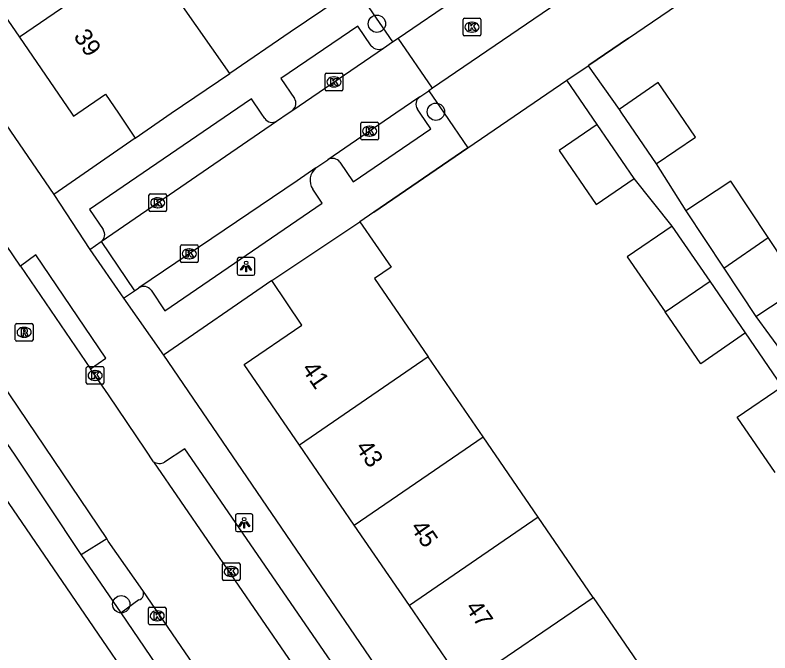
# Model space of a CAD drawing. Extents: x 157466 to 158888, y 383063 to 384677.
# Drawn here: x 158131.78 to 158174.52, y 383719.45 to 383755.56 of the extents above; entities that cross this region are included whole.
import ezdxf

# ---------------------------------------------------------------- set-up
doc = ezdxf.new("R2010")
doc.units = 0
for name, color, linetype in [('IMGEO_Boom', 7, 'Continuous'), ('IMGEO_Kolk', 7, 'Continuous'), ('IMGEO_Lichtpunt', 7, 'Continuous'), ('IMGEO_Muur', 7, 'Continuous'), ('IMGEO_Pand', 7, 'Continuous'), ('IMGEO_Pand_nummerreeks', 7, 'Continuous'), ('IMGEO_Parkeervlak_open', 7, 'Continuous'), ('IMGEO_Rijbaan_lokaal_open', 7, 'Continuous'), ('IMGEO_Rioolput', 7, 'Continuous'), ('IMGEO_Voetpad_open', 7, 'Continuous')]:
    doc.layers.add(name, color=color, linetype=linetype)

msp = doc.modelspace()

# ---------------------------------------------------------------- linework, layer by layer
at = {"layer": 'IMGEO_Boom'}
for centre in [(158152.265, 383755.066), (158155.606, 383750.086), (158137.79, 383722.2)]:
    msp.add_circle(centre, 0.489, dxfattribs=at)
at = {"layer": 'IMGEO_Kolk'}
for p, q in [((158157.15, 383754.45), (158157.15, 383755.302)), ((158157.225, 383755.376), (158158.077, 383755.376)), ((158158.151, 383755.302), (158158.151, 383754.45)), ((158157.638, 383755.156), (158157.663, 383755.156)), ((158158.077, 383754.376), (158157.225, 383754.376)), ((158157.661, 383754.596), (158157.636, 383754.596)), ((158149.41, 383752.274), (158150.262, 383752.274)), ((158149.335, 383751.348), (158149.335, 383752.2)), ((158149.823, 383752.054), (158149.848, 383752.054)), ((158150.336, 383752.2), (158150.336, 383751.348)), ((158149.846, 383751.494), (158149.821, 383751.494)), ((158150.262, 383751.274), (158149.41, 383751.274)), ((158151.355, 383748.56), (158151.355, 383749.412)), ((158151.43, 383749.486), (158152.282, 383749.486)), ((158151.843, 383749.266), (158151.868, 383749.266)), ((158152.356, 383749.412), (158152.356, 383748.56)), ((158152.282, 383748.486), (158151.43, 383748.486)), ((158151.866, 383748.706), (158151.841, 383748.706)), ((158139.435, 383745.431), (158140.287, 383745.431)), ((158139.36, 383744.505), (158139.36, 383745.357)), ((158139.848, 383745.211), (158139.873, 383745.211)), ((158140.361, 383745.357), (158140.361, 383744.505)), ((158139.871, 383744.651), (158139.846, 383744.651)), ((158140.287, 383744.431), (158139.435, 383744.431)), ((158141.143, 383741.617), (158141.143, 383742.469)), ((158141.218, 383742.543), (158142.07, 383742.543)), ((158142.144, 383742.469), (158142.144, 383741.617)), ((158141.631, 383742.323), (158141.656, 383742.323)), ((158141.654, 383741.763), (158141.629, 383741.763)), ((158142.07, 383741.543), (158141.218, 383741.543)), ((158135.813, 383734.728), (158135.813, 383735.58)), ((158135.888, 383735.654), (158136.74, 383735.654)), ((158136.814, 383735.58), (158136.814, 383734.728)), ((158136.301, 383735.434), (158136.326, 383735.434)), ((158136.324, 383734.874), (158136.299, 383734.874)), ((158136.74, 383734.654), (158135.888, 383734.654)), ((158143.515, 383723.625), (158143.515, 383724.477)), ((158143.59, 383724.551), (158144.442, 383724.551)), ((158144.516, 383724.477), (158144.516, 383723.625)), ((158144.003, 383724.331), (158144.028, 383724.331)), ((158144.026, 383723.771), (158144.001, 383723.771)), ((158144.442, 383723.551), (158143.59, 383723.551)), ((158139.325, 383721.116), (158139.325, 383721.968)), ((158139.4, 383722.042), (158140.252, 383722.042)), ((158140.326, 383721.968), (158140.326, 383721.116)), ((158139.813, 383721.822), (158139.838, 383721.822)), ((158140.252, 383721.042), (158139.4, 383721.042)), ((158139.836, 383721.262), (158139.811, 383721.262))]:
    msp.add_line(p, q, dxfattribs=at)
for points in [[(158157.15, 383754.45), (158157.15, 383755.302)], [(158157.225, 383755.376), (158158.077, 383755.376)], [(158158.151, 383755.302), (158158.151, 383754.45)], [(158157.471, 383755.076), (158157.594, 383755.076), (158157.594, 383754.925), (158157.724, 383755.076), (158157.888, 383755.076), (158157.742, 383754.925), (158157.895, 383754.676), (158157.743, 383754.676), (158157.658, 383754.84), (158157.594, 383754.773), (158157.594, 383754.676), (158157.471, 383754.676), (158157.471, 383755.076)], [(158158.077, 383754.376), (158157.225, 383754.376)], [(158149.41, 383752.274), (158150.262, 383752.274)], [(158149.335, 383751.348), (158149.335, 383752.2)], [(158149.656, 383751.974), (158149.779, 383751.974), (158149.779, 383751.823), (158149.909, 383751.974), (158150.073, 383751.974), (158149.927, 383751.823), (158150.08, 383751.574), (158149.928, 383751.574), (158149.843, 383751.738), (158149.779, 383751.671), (158149.779, 383751.574), (158149.656, 383751.574), (158149.656, 383751.974)], [(158150.336, 383752.2), (158150.336, 383751.348)], [(158150.262, 383751.274), (158149.41, 383751.274)], [(158151.355, 383748.56), (158151.355, 383749.412)], [(158151.43, 383749.486), (158152.282, 383749.486)], [(158152.356, 383749.412), (158152.356, 383748.56)], [(158151.676, 383749.186), (158151.799, 383749.186), (158151.799, 383749.035), (158151.929, 383749.186), (158152.093, 383749.186), (158151.947, 383749.035), (158152.1, 383748.786), (158151.948, 383748.786), (158151.863, 383748.95), (158151.799, 383748.883), (158151.799, 383748.786), (158151.676, 383748.786), (158151.676, 383749.186)], [(158152.282, 383748.486), (158151.43, 383748.486)], [(158139.435, 383745.431), (158140.287, 383745.431)], [(158139.36, 383744.505), (158139.36, 383745.357)], [(158139.681, 383745.131), (158139.804, 383745.131), (158139.804, 383744.98), (158139.934, 383745.131), (158140.098, 383745.131), (158139.952, 383744.98), (158140.105, 383744.731), (158139.953, 383744.731), (158139.868, 383744.895), (158139.804, 383744.828), (158139.804, 383744.731), (158139.681, 383744.731), (158139.681, 383745.131)], [(158140.361, 383745.357), (158140.361, 383744.505)], [(158140.287, 383744.431), (158139.435, 383744.431)], [(158141.143, 383741.617), (158141.143, 383742.469)], [(158141.218, 383742.543), (158142.07, 383742.543)], [(158142.144, 383742.469), (158142.144, 383741.617)], [(158141.464, 383742.243), (158141.587, 383742.243), (158141.587, 383742.092), (158141.717, 383742.243), (158141.881, 383742.243), (158141.735, 383742.092), (158141.888, 383741.843), (158141.736, 383741.843), (158141.651, 383742.007), (158141.587, 383741.94), (158141.587, 383741.843), (158141.464, 383741.843), (158141.464, 383742.243)], [(158142.07, 383741.543), (158141.218, 383741.543)], [(158135.813, 383734.728), (158135.813, 383735.58)], [(158135.888, 383735.654), (158136.74, 383735.654)], [(158136.814, 383735.58), (158136.814, 383734.728)], [(158136.134, 383735.354), (158136.257, 383735.354), (158136.257, 383735.203), (158136.387, 383735.354), (158136.551, 383735.354), (158136.405, 383735.203), (158136.558, 383734.954), (158136.406, 383734.954), (158136.321, 383735.118), (158136.257, 383735.051), (158136.257, 383734.954), (158136.134, 383734.954), (158136.134, 383735.354)], [(158136.74, 383734.654), (158135.888, 383734.654)], [(158143.515, 383723.625), (158143.515, 383724.477)], [(158143.59, 383724.551), (158144.442, 383724.551)], [(158144.516, 383724.477), (158144.516, 383723.625)], [(158143.836, 383724.251), (158143.959, 383724.251), (158143.959, 383724.1), (158144.089, 383724.251), (158144.253, 383724.251), (158144.107, 383724.1), (158144.26, 383723.851), (158144.108, 383723.851), (158144.023, 383724.015), (158143.959, 383723.948), (158143.959, 383723.851), (158143.836, 383723.851), (158143.836, 383724.251)], [(158144.442, 383723.551), (158143.59, 383723.551)], [(158139.325, 383721.116), (158139.325, 383721.968)], [(158139.4, 383722.042), (158140.252, 383722.042)], [(158140.326, 383721.968), (158140.326, 383721.116)], [(158139.646, 383721.742), (158139.769, 383721.742), (158139.769, 383721.591), (158139.899, 383721.742), (158140.063, 383721.742), (158139.917, 383721.591), (158140.07, 383721.342), (158139.918, 383721.342), (158139.833, 383721.506), (158139.769, 383721.439), (158139.769, 383721.342), (158139.646, 383721.342), (158139.646, 383721.742)], [(158140.252, 383721.042), (158139.4, 383721.042)]]:
    msp.add_lwpolyline(points, dxfattribs=at)
for centre, start, end in [((158157.227, 383755.3), 91.552, 178.448), ((158157.227, 383755.3), 91.552, 178.448), ((158158.075, 383755.3), 1.552, 88.448), ((158158.075, 383755.3), 1.552, 88.448), ((158157.227, 383754.452), 181.552, 268.448), ((158157.227, 383754.452), 181.552, 268.448), ((158158.075, 383754.452), 271.552, 358.448), ((158158.075, 383754.452), 271.552, 358.448), ((158149.412, 383752.198), 91.552, 178.448), ((158149.412, 383752.198), 91.552, 178.448), ((158150.26, 383752.198), 1.552, 88.448), ((158150.26, 383752.198), 1.552, 88.448), ((158149.412, 383751.35), 181.552, 268.448), ((158149.412, 383751.35), 181.552, 268.448), ((158150.26, 383751.35), 271.552, 358.448), ((158150.26, 383751.35), 271.552, 358.448), ((158151.432, 383749.41), 91.552, 178.448), ((158151.432, 383749.41), 91.552, 178.448), ((158152.28, 383749.41), 1.552, 88.448), ((158152.28, 383749.41), 1.552, 88.448), ((158151.432, 383748.562), 181.552, 268.448), ((158151.432, 383748.562), 181.552, 268.448), ((158152.28, 383748.562), 271.552, 358.448), ((158152.28, 383748.562), 271.552, 358.448), ((158139.437, 383745.355), 91.552, 178.448), ((158139.437, 383745.355), 91.552, 178.448), ((158140.285, 383745.355), 1.552, 88.448), ((158140.285, 383745.355), 1.552, 88.448), ((158139.437, 383744.507), 181.552, 268.448), ((158139.437, 383744.507), 181.552, 268.448), ((158140.285, 383744.507), 271.552, 358.448), ((158140.285, 383744.507), 271.552, 358.448), ((158141.22, 383742.467), 91.552, 178.448), ((158141.22, 383742.467), 91.552, 178.448), ((158142.068, 383742.467), 1.552, 88.448), ((158142.068, 383742.467), 1.552, 88.448), ((158141.22, 383741.619), 181.552, 268.448), ((158141.22, 383741.619), 181.552, 268.448), ((158142.068, 383741.619), 271.552, 358.448), ((158142.068, 383741.619), 271.552, 358.448), ((158135.89, 383735.578), 91.552, 178.448), ((158135.89, 383735.578), 91.552, 178.448), ((158136.738, 383735.578), 1.552, 88.448), ((158136.738, 383735.578), 1.552, 88.448), ((158135.89, 383734.73), 181.552, 268.448), ((158135.89, 383734.73), 181.552, 268.448), ((158136.738, 383734.73), 271.552, 358.448), ((158136.738, 383734.73), 271.552, 358.448), ((158143.592, 383724.475), 91.552, 178.448), ((158143.592, 383724.475), 91.552, 178.448), ((158144.44, 383724.475), 1.552, 88.448), ((158144.44, 383724.475), 1.552, 88.448), ((158143.592, 383723.627), 181.552, 268.448), ((158143.592, 383723.627), 181.552, 268.448), ((158144.44, 383723.627), 271.552, 358.448), ((158144.44, 383723.627), 271.552, 358.448), ((158139.402, 383721.966), 91.552, 178.448), ((158139.402, 383721.966), 91.552, 178.448), ((158140.25, 383721.966), 1.552, 88.448), ((158140.25, 383721.966), 1.552, 88.448), ((158139.402, 383721.118), 181.552, 268.448), ((158139.402, 383721.118), 181.552, 268.448), ((158140.25, 383721.118), 271.552, 358.448), ((158140.25, 383721.118), 271.552, 358.448)]:
    msp.add_arc(centre, 0.0765, start, end, dxfattribs=at)
for centre, major_axis, ratio, start_param, end_param in [((158157.637, 383754.876), (-0.387, 0.002), 0.722429, 4.712389, 7.853982), ((158157.662, 383754.876), (-0.39, 0.002), 0.717154, 1.570796, 4.712389), ((158149.822, 383751.774), (-0.387, 0.002), 0.722429, 4.712389, 7.853982), ((158149.847, 383751.774), (-0.39, 0.002), 0.717154, 1.570796, 4.712389), ((158151.842, 383748.986), (-0.387, 0.002), 0.722429, 4.712389, 7.853982), ((158151.867, 383748.986), (-0.39, 0.002), 0.717154, 1.570796, 4.712389), ((158139.847, 383744.931), (-0.387, 0.002), 0.722429, 4.712389, 7.853982), ((158139.872, 383744.931), (-0.39, 0.002), 0.717154, 1.570796, 4.712389), ((158141.63, 383742.043), (-0.387, 0.002), 0.722429, 4.712389, 7.853982), ((158141.655, 383742.043), (-0.39, 0.002), 0.717154, 1.570796, 4.712389), ((158136.3, 383735.154), (-0.387, 0.002), 0.722429, 4.712389, 7.853982), ((158136.325, 383735.154), (-0.39, 0.002), 0.717154, 1.570796, 4.712389), ((158144.002, 383724.051), (-0.387, 0.002), 0.722429, 4.712389, 7.853982), ((158144.027, 383724.051), (-0.39, 0.002), 0.717154, 1.570796, 4.712389), ((158139.812, 383721.542), (-0.387, 0.002), 0.722429, 4.712389, 7.853982), ((158139.837, 383721.542), (-0.39, 0.002), 0.717154, 1.570796, 4.712389)]:
    msp.add_ellipse(centre, major_axis=major_axis, ratio=ratio, start_param=start_param, end_param=end_param, dxfattribs=at)
at = {"layer": 'IMGEO_Lichtpunt'}
for p, q in [((158144.362, 383741.732), (158144.362, 383740.925)), ((158144.362, 383741.732), (158144.362, 383740.925)), ((158145.264, 383741.827), (158144.456, 383741.827)), ((158145.264, 383741.827), (158144.456, 383741.827)), ((158145.358, 383740.925), (158145.358, 383741.732)), ((158145.358, 383740.925), (158145.358, 383741.732)), ((158144.456, 383740.831), (158145.264, 383740.831)), ((158144.456, 383740.831), (158145.264, 383740.831)), ((158144.254, 383727.217), (158144.254, 383726.41)), ((158144.254, 383727.217), (158144.254, 383726.41)), ((158145.156, 383727.312), (158144.348, 383727.312)), ((158145.156, 383727.312), (158144.348, 383727.312)), ((158145.25, 383726.41), (158145.25, 383727.217)), ((158145.25, 383726.41), (158145.25, 383727.217)), ((158144.348, 383726.316), (158145.156, 383726.316)), ((158144.348, 383726.316), (158145.156, 383726.316))]:
    msp.add_line(p, q, dxfattribs=at)
for points in [[(158144.736, 383741.396), (158144.775, 383741.368), (158144.587, 383741.106), (158144.549, 383741.133), (158144.736, 383741.396)], [(158144.838, 383741.348), (158144.885, 383741.348), (158144.885, 383741.026), (158144.838, 383741.026), (158144.838, 383741.348)], [(158144.948, 383741.368), (158144.986, 383741.395), (158145.173, 383741.133), (158145.134, 383741.105), (158144.948, 383741.368)], [(158144.628, 383726.881), (158144.667, 383726.853), (158144.479, 383726.591), (158144.441, 383726.618), (158144.628, 383726.881)], [(158144.73, 383726.833), (158144.777, 383726.833), (158144.777, 383726.511), (158144.73, 383726.511), (158144.73, 383726.833)], [(158144.84, 383726.853), (158144.878, 383726.88), (158145.065, 383726.618), (158145.026, 383726.59), (158144.84, 383726.853)]]:
    msp.add_lwpolyline(points, dxfattribs=at)
for centre in [(158144.861, 383741.53), (158144.753, 383727.015)]:
    msp.add_circle(centre, 0.0994, dxfattribs=at)
for centre, start, end in [((158144.456, 383741.732), 90, 180), ((158144.456, 383741.732), 90, 180), ((158145.264, 383741.732), 0, 90), ((158145.264, 383741.732), 0, 90), ((158144.456, 383740.925), 180, 270), ((158144.456, 383740.925), 180, 270), ((158145.264, 383740.925), 270, 0), ((158145.264, 383740.925), 270, 360), ((158144.348, 383727.217), 90, 180), ((158144.348, 383727.217), 90, 180), ((158145.156, 383727.217), 0, 90), ((158145.156, 383727.217), 0, 90), ((158144.348, 383726.41), 180, 270), ((158144.348, 383726.41), 180, 270), ((158145.156, 383726.41), 270, 0), ((158145.156, 383726.41), 270, 360)]:
    msp.add_arc(centre, 0.0946, start, end, dxfattribs=at)
at = {"layer": 'IMGEO_Muur'}
for points in [[(158166.506, 383754.251), (158164.262, 383752.715)], [(158157.421, 383748.033), (158163.021, 383751.865)], [(158152.1, 383744.39), (158157.421, 383748.033)]]:
    msp.add_lwpolyline(points, dxfattribs=at)
at = {"layer": 'IMGEO_Pand'}
for points in [[(158139.1, 383759.157), (158132.021, 383754.315)], [(158143.934, 383752.254), (158139.1, 383759.157)], [(158128.922, 383758.845), (158132.021, 383754.315)], [(158132.021, 383754.315), (158134.972, 383750), (158135.086, 383749.834), (158135.326, 383750), (158136.894, 383751.084), (158137.627, 383750), (158138.577, 383748.596)], [(158138.577, 383748.596), (158140.625, 383750), (158143.934, 383752.254)], [(158168.085, 383747.132), (158170.305, 383748.653), (158169.384, 383750), (158168.196, 383751.739), (158165.975, 383750.213)], [(158165.975, 383750.213), (158166.121, 383750), (158168.085, 383747.132)], [(158164.736, 383749.362), (158162.59, 383747.892), (158164.686, 383744.832), (158166.832, 383746.303)], [(158166.832, 383746.303), (158164.736, 383749.362)], [(158174.421, 383742.96), (158172.298, 383746.162), (158169.758, 383744.477)], [(158169.758, 383744.477), (158171.907, 383741.236)], [(158146.314, 383740.523), (158151.309, 383743.861)], [(158151.309, 383743.861), (158153.074, 383741.289), (158152.122, 383740.636), (158155.162, 383736.206)], [(158168.978, 383743.612), (158166.445, 383741.869), (158168.593, 383738.747)], [(158171.129, 383740.486), (158168.978, 383743.612)], [(158171.907, 383741.236), (158174.421, 383742.96)], [(158173.727, 383738.491), (158176.267, 383740.175), (158174.421, 383742.96)], [(158171.907, 383741.236), (158173.727, 383738.491)], [(158147.876, 383731.209), (158144.744, 383735.777), (158148.025, 383738.008), (158146.314, 383740.523)], [(158168.593, 383738.747), (158171.129, 383740.486)], [(158173.142, 383737.56), (158171.129, 383740.486)], [(158173.142, 383737.56), (158170.609, 383735.817), (158168.593, 383738.747)], [(158155.162, 383736.206), (158147.876, 383731.209)], [(158158.274, 383731.67), (158155.162, 383736.206)], [(158174.823, 383729.666), (158172.674, 383732.789), (158175.207, 383734.532)], [(158150.986, 383726.672), (158158.274, 383731.67)], [(158161.393, 383727.123), (158158.274, 383731.67)], [(158150.986, 383726.672), (158147.876, 383731.209)], [(158161.393, 383727.123), (158154.104, 383722.125)], [(158164.503, 383722.59), (158161.393, 383727.123)], [(158154.104, 383722.125), (158150.986, 383726.672)], [(158157.213, 383717.591), (158164.503, 383722.59)], [(158164.503, 383722.59), (158167.678, 383717.963)], [(158157.213, 383717.591), (158154.104, 383722.125)]]:
    msp.add_lwpolyline(points, dxfattribs=at)
at = {"layer": 'IMGEO_Parkeervlak_open'}
for points in [[(158135.513, 383725.021), (158136.966, 383725.919)], [(158138.793, 383722.447), (158137.78, 383721.718)]]:
    msp.add_lwpolyline(points, dxfattribs=at)
msp.add_arc((158138.689, 383722.801), 0.369, 286.2975, 28.4321, dxfattribs=at)
at = {"layer": 'IMGEO_Rijbaan_lokaal_open'}
for points in [[(158153.468, 383754.255), (158163.604, 383761.185)], [(158165.587, 383758.374), (158155.41, 383751.416)], [(158152.646, 383753.693), (158153.152, 383754.039)], [(158153.152, 383754.039), (158153.468, 383754.255)], [(158155.41, 383751.416), (158153.468, 383754.255)], [(158147.501, 383750.176), (158152.646, 383753.693)], [(158155.41, 383751.416), (158155.205, 383751.276)], [(158154.689, 383750.924), (158155.205, 383751.276)], [(158154.689, 383750.924), (158153.338, 383750), (158149.491, 383747.37)], [(158146.587, 383749.548), (158147.245, 383750), (158147.501, 383750.176)], [(158136.657, 383742.731), (158146.587, 383749.548)], [(158148.813, 383746.907), (158149.491, 383747.37)], [(158148.813, 383746.907), (158147.744, 383746.176), (158138.788, 383740.11)], [(158132.093, 383741.351), (158130.874, 383743.091), (158128.732, 383746.298)], [(158136.966, 383725.919), (158124.947, 383743.707)], [(158136.012, 383742.288), (158136.657, 383742.731)], [(158136.657, 383742.731), (158138.533, 383739.937)], [(158136.012, 383742.288), (158137.923, 383739.524)], [(158132.093, 383741.351), (158136.056, 383735.537)], [(158137.923, 383739.524), (158138.533, 383739.937)], [(158138.533, 383739.937), (158138.788, 383740.11)], [(158139.617, 383730.272), (158139.182, 383730.933), (158137.076, 383734.051), (158136.056, 383735.537)], [(158139.617, 383730.272), (158156.428, 383705.77)], [(158139.014, 383722.977), (158137.06, 383725.779), (158136.966, 383725.919)], [(158143.805, 383715.982), (158139.014, 383722.977)]]:
    msp.add_lwpolyline(points, dxfattribs=at)
at = {"layer": 'IMGEO_Rioolput'}
for p, q in [((158131.794, 383737.173), (158131.794, 383738.025)), ((158131.869, 383738.099), (158132.721, 383738.099)), ((158132.282, 383737.879), (158132.307, 383737.879)), ((158132.795, 383738.025), (158132.795, 383737.173)), ((158132.305, 383737.319), (158132.28, 383737.319)), ((158132.721, 383737.099), (158131.869, 383737.099))]:
    msp.add_line(p, q, dxfattribs=at)
for points in [[(158131.794, 383737.173), (158131.794, 383738.025)], [(158131.869, 383738.099), (158132.721, 383738.099)], [(158132.383, 383737.797), (158132.131, 383737.799), (158132.131, 383737.399)], [(158132.309, 383737.718), (158132.255, 383737.718), (158132.255, 383737.637)], [(158132.795, 383738.025), (158132.795, 383737.173)], [(158132.131, 383737.399), (158132.255, 383737.399), (158132.255, 383737.561), (158132.266, 383737.561)], [(158132.255, 383737.637), (158132.307, 383737.637)], [(158132.313, 383737.532), (158132.384, 383737.399), (158132.524, 383737.399), (158132.459, 383737.525)], [(158132.721, 383737.099), (158131.869, 383737.099)]]:
    msp.add_lwpolyline(points, dxfattribs=at)
for centre, radius, start, end in [((158131.871, 383738.023), 0.0765, 91.552, 178.448), ((158131.871, 383738.023), 0.0765, 91.552, 178.448), ((158132.315, 383737.622), 0.0964, 77.0061, 93.1865), ((158132.329, 383737.679), 0.0378, 276.6634, 79.6772), ((158132.382, 383737.687), 0.109, 350.3612, 89.416), ((158132.719, 383738.023), 0.0765, 1.552, 88.448), ((158132.719, 383738.023), 0.0765, 1.552, 88.448), ((158132.265, 383737.508), 0.0533, 26.0293, 88.6989), ((158132.291, 383737.826), 0.19, 274.7715, 282.9687), ((158132.38, 383737.687), 0.112, 277.5842, 350.9817), ((158132.364, 383737.472), 0.108, 29.5134, 73.7905), ((158131.871, 383737.175), 0.0765, 181.552, 268.448), ((158131.871, 383737.175), 0.0765, 181.552, 268.448), ((158132.719, 383737.175), 0.0765, 271.552, 358.448), ((158132.719, 383737.175), 0.0765, 271.552, 358.448)]:
    msp.add_arc(centre, radius, start, end, dxfattribs=at)
for centre, major_axis, ratio, start_param, end_param in [((158132.281, 383737.599), (-0.387, 0.002), 0.722429, 4.712389, 7.853982), ((158132.306, 383737.599), (-0.39, 0.002), 0.717154, 1.570796, 4.712389)]:
    msp.add_ellipse(centre, major_axis=major_axis, ratio=ratio, start_param=start_param, end_param=end_param, dxfattribs=at)
at = {"layer": 'IMGEO_Voetpad_open'}
for points in [[(158100.07, 383794.919), (158133.967, 383745.394)], [(158151.062, 383757.099), (158147.354, 383754.586), (158143.934, 383752.254)], [(158151.062, 383757.099), (158153.152, 383754.039)], [(158164.227, 383752.691), (158164.262, 383752.715), (158166.506, 383754.251), (158169.708, 383756.443)], [(158112.77, 383755.176), (158115.18, 383751.638), (158159.53, 383686.796)], [(158151.951, 383753.824), (158151.191, 383754.937), (158146.834, 383751.958), (158147.596, 383750.843)], [(158163.021, 383751.865), (158164.227, 383752.691)], [(158164.227, 383752.691), (158165.975, 383750.213)], [(158157.421, 383748.033), (158163.021, 383751.865)], [(158164.736, 383749.362), (158163.021, 383751.865)], [(158155.205, 383751.276), (158156.077, 383750), (158157.421, 383748.033)], [(158145.925, 383749.7), (158145.72, 383750), (158145.163, 383750.815), (158143.971, 383750), (158135.993, 383744.545), (158136.767, 383743.412)], [(158150.166, 383747.226), (158150.927, 383746.112), (158155.323, 383749.117), (158154.72, 383750), (158154.562, 383750.231)], [(158138.577, 383748.596), (158133.967, 383745.394)], [(158157.421, 383748.033), (158152.1, 383744.39), (158151.309, 383743.861)], [(158135.513, 383725.021), (158131.783, 383730.632), (158120.407, 383747.209)], [(158168.085, 383747.132), (158169.758, 383744.477)], [(158168.978, 383743.612), (158166.832, 383746.303)], [(158133.967, 383745.394), (158136.012, 383742.288)], [(158139.476, 383739.975), (158140.263, 383738.822), (158149.173, 383744.914), (158148.635, 383745.702)], [(158136.056, 383735.537), (158136.927, 383736.134), (158132.961, 383741.981), (158132.093, 383741.351)], [(158146.314, 383740.523), (158140.184, 383736.308)], [(158137.923, 383739.524), (158140.184, 383736.308)], [(158173.727, 383738.491), (158176.038, 383735.315)], [(158175.207, 383734.532), (158173.142, 383737.56)], [(158140.184, 383736.308), (158160.467, 383706.551)], [(158156.546, 383706.454), (158157.714, 383707.264), (158141.391, 383730.996), (158140.243, 383730.247)], [(158137.78, 383721.718), (158135.513, 383725.021)], [(158142.146, 383715.294), (158137.78, 383721.718)]]:
    msp.add_lwpolyline(points, dxfattribs=at)
for centre, radius, start, end in [((158152.371, 383754.144), 0.528, 217.2771, 301.3741), ((158147.184, 383750.561), 0.499, 309.4487, 34.3392), ((158154.972, 383750.514), 0.498, 124.6121, 214.6182), ((158146.338, 383749.98), 0.499, 214.174, 299.9633), ((158149.753, 383746.943), 0.501, 34.3725, 121.5424), ((158149.375, 383746.208), 0.897, 128.8251, 214.3692), ((158136.353, 383743.129), 0.501, 307.301, 34.3479), ((158139.063, 383739.692), 0.501, 34.4419, 123.3549), ((158139.951, 383730.782), 0.61, 236.8085, 298.6176)]:
    msp.add_arc(centre, radius, start, end, dxfattribs=at)

# ---------------------------------------------------------------- texts
at = {"layer": 'IMGEO_Pand_nummerreeks'}
for s, rotation, p in [('39', 304.3715, (158135.057, 383754.341)), ('41', 304.4346, (158147.974, 383735.522)), ('43', 304.4354, (158151.021, 383731.078)), ('45', 304.4354, (158154.131, 383726.541)), ('47', 304.4354, (158157.242, 383722.004))]:
    msp.add_text(s, height=1, rotation=rotation, dxfattribs=at).set_placement(p)

doc.saveas('drawing.dxf')
